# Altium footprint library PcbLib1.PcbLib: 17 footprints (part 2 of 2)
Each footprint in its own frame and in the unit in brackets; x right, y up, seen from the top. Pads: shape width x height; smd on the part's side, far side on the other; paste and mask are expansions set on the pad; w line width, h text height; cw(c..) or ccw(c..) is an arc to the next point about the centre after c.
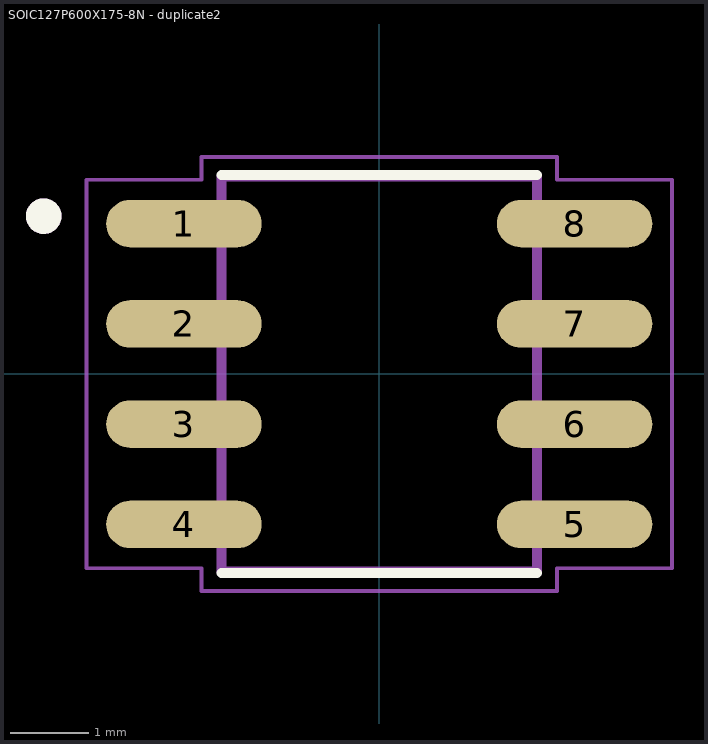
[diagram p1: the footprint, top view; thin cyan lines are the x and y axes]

## SOIC127P600X175-8N - duplicate2 [mm]
pads (8):
  oval 1.97x0.6 smd: 1(-2.475,1.905) 2(-2.475,0.635) 3(-2.475,-0.635) 4(-2.475,-1.905) 5(2.475,-1.905) 6(2.475,-0.635) 7(2.475,0.635) 8(2.475,1.905)
Top Overlay:
  circle w0.25: c-4.25,2 r0.1
  lines w0.127: -2,-2.519 2,-2.519 ; -2,2.519 2,2.519
Mechanical 13:
  circle w0.25: c-4.25,2 r0.1
  lines w0.127: -2,-2.5 2,-2.5 2,2.5 -2,2.5 -2,-2.5
Mechanical 15:
  lines w0.05: -3.71,-2.46 -2.25,-2.46 -2.25,-2.75 2.25,-2.75 2.25,-2.46 3.71,-2.46 3.71,2.46 2.25,2.46 2.25,2.75 -2.25,2.75 -2.25,2.46 -3.71,2.46 -3.71,-2.46
3D body "step_temp.STEP": height 1.75, standoff 0, extent -3,-2.45 3,2.45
